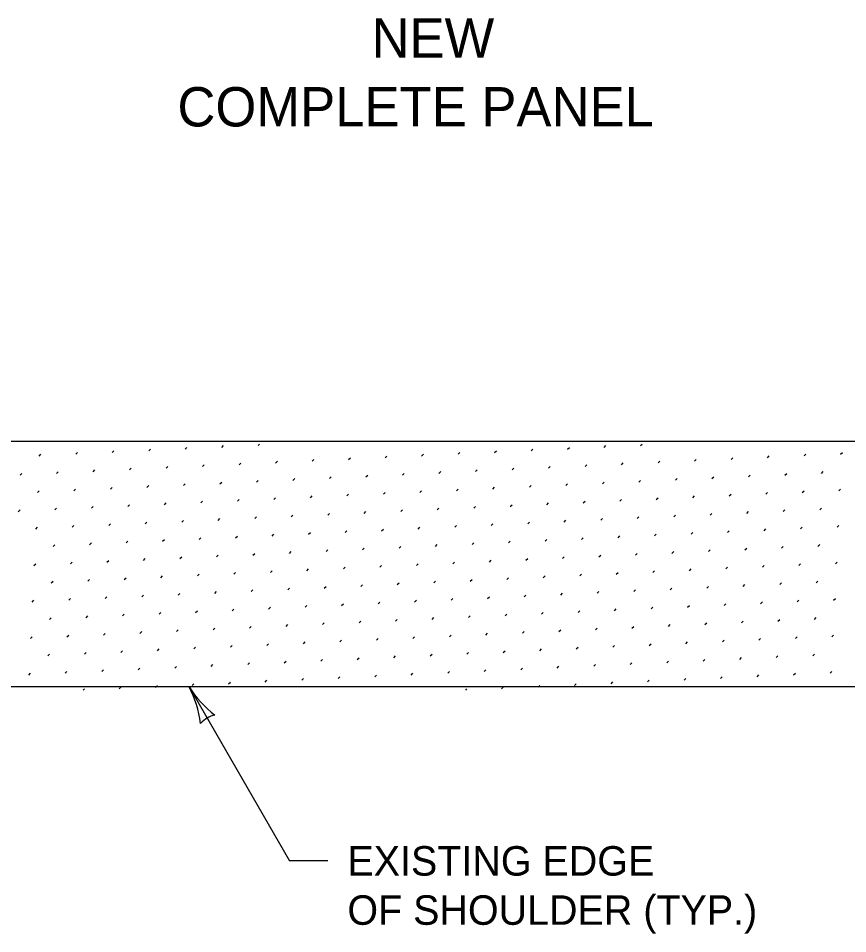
# Model space of a CAD drawing. Extents: x 49991.4 to 50021, y 49987.6 to 50011.4.
# Drawn here: x 50009.904 to 50011.591, y 49993.788 to 49995.65 of the extents above; entities that cross this region are included whole.
import ezdxf

# ---------------------------------------------------------------- set-up
doc = ezdxf.new("R2010")
doc.units = 0
for name, color, linetype in [('Level 1', 7, 'Continuous'), ('Level 10', 7, 'Continuous'), ('Level 2', 7, 'Continuous'), ('Level 3', 7, 'Continuous')]:
    doc.layers.add(name, color=color, linetype=linetype)

msp = doc.modelspace()

# ---------------------------------------------------------------- linework, layer by layer
at = {"layer": 'Level 1'}
for p, q in [((50009.8098, 49994.7903), (50011.6848, 49994.7903)), ((50015.1301, 49994.2903), (50001.3364, 49994.2903))]:
    msp.add_line(p, q, dxfattribs=at)
at = {"layer": 'Level 10'}
for p, q in [((50010.392, 49994.781), (50010.3949, 49994.7838)), ((50011.1699, 49994.7811), (50011.1727, 49994.7838)), ((50010.0208, 49994.7633), (50010.0243, 49994.7668)), ((50010.095, 49994.7668), (50010.0985, 49994.7704)), ((50010.1693, 49994.7704), (50010.1728, 49994.7739)), ((50010.2435, 49994.7739), (50010.247, 49994.7774)), ((50010.3178, 49994.7775), (50010.3213, 49994.781)), ((50010.7986, 49994.7634), (50010.8022, 49994.7669)), ((50010.8729, 49994.7669), (50010.8764, 49994.7704)), ((50010.9471, 49994.7704), (50010.9507, 49994.774)), ((50011.0214, 49994.774), (50011.0249, 49994.7775)), ((50011.0957, 49994.7775), (50011.0992, 49994.7811)), ((50011.5765, 49994.7634), (50011.5801, 49994.767)), ((50009.9465, 49994.7597), (50009.95, 49994.7633)), ((50010.3531, 49994.7421), (50010.3567, 49994.7456)), ((50010.4274, 49994.7456), (50010.4309, 49994.7492)), ((50010.5016, 49994.7492), (50010.5052, 49994.7527)), ((50010.5759, 49994.7527), (50010.5794, 49994.7563)), ((50010.6501, 49994.7563), (50010.6537, 49994.7598)), ((50010.7244, 49994.7598), (50010.7279, 49994.7633)), ((50011.131, 49994.7422), (50011.1345, 49994.7457)), ((50011.2053, 49994.7457), (50011.2088, 49994.7492)), ((50011.2795, 49994.7493), (50011.2831, 49994.7528)), ((50011.3538, 49994.7528), (50011.3573, 49994.7563)), ((50011.428, 49994.7563), (50011.4316, 49994.7599)), ((50011.5023, 49994.7599), (50011.5058, 49994.7634)), ((50009.9819, 49994.7244), (50009.9854, 49994.7279)), ((50010.0561, 49994.7279), (50010.0596, 49994.7315)), ((50010.1304, 49994.7315), (50010.1339, 49994.735)), ((50010.2046, 49994.735), (50010.2082, 49994.7385)), ((50010.2789, 49994.7386), (50010.2824, 49994.7421)), ((50010.7597, 49994.7245), (50010.7633, 49994.728)), ((50010.834, 49994.728), (50010.8375, 49994.7315)), ((50010.9082, 49994.7315), (50010.9118, 49994.7351)), ((50010.9825, 49994.7351), (50010.986, 49994.7386)), ((50011.0568, 49994.7386), (50011.0603, 49994.7422)), ((50011.5376, 49994.7245), (50011.5412, 49994.7281)), ((50009.9076, 49994.7208), (50009.9111, 49994.7244)), ((50010.3885, 49994.7067), (50010.392, 49994.7103)), ((50010.4627, 49994.7103), (50010.4663, 49994.7138)), ((50010.537, 49994.7138), (50010.5405, 49994.7174)), ((50010.6112, 49994.7174), (50010.6148, 49994.7209)), ((50010.6855, 49994.7209), (50010.689, 49994.7244)), ((50011.1664, 49994.7068), (50011.1699, 49994.7103)), ((50011.2406, 49994.7104), (50011.2442, 49994.7139)), ((50011.3149, 49994.7139), (50011.3184, 49994.7174)), ((50011.3891, 49994.7174), (50011.3927, 49994.721)), ((50011.4634, 49994.721), (50011.4669, 49994.7245)), ((50010.0172, 49994.689), (50010.0207, 49994.6926)), ((50010.0915, 49994.6926), (50010.095, 49994.6961)), ((50010.1657, 49994.6961), (50010.1693, 49994.6996)), ((50010.24, 49994.6997), (50010.2435, 49994.7032)), ((50010.3142, 49994.7032), (50010.3178, 49994.7067)), ((50010.7951, 49994.6891), (50010.7986, 49994.6926)), ((50010.8694, 49994.6926), (50010.8729, 49994.6962)), ((50010.9436, 49994.6962), (50010.9471, 49994.6997)), ((50011.0179, 49994.6997), (50011.0214, 49994.7033)), ((50011.0921, 49994.7033), (50011.0956, 49994.7068)), ((50011.573, 49994.6892), (50011.5765, 49994.6927)), ((50009.943, 49994.6855), (50009.9465, 49994.689)), ((50010.3496, 49994.6678), (50010.3531, 49994.6714)), ((50010.4238, 49994.6714), (50010.4274, 49994.6749)), ((50010.4981, 49994.6749), (50010.5016, 49994.6785)), ((50010.5723, 49994.6785), (50010.5759, 49994.682)), ((50010.6466, 49994.682), (50010.6501, 49994.6855)), ((50010.7208, 49994.6856), (50010.7244, 49994.6891)), ((50011.1275, 49994.6679), (50011.131, 49994.6714)), ((50011.2017, 49994.6715), (50011.2053, 49994.675)), ((50011.276, 49994.675), (50011.2795, 49994.6785)), ((50011.3502, 49994.6785), (50011.3538, 49994.6821)), ((50011.4245, 49994.6821), (50011.428, 49994.6856)), ((50011.4987, 49994.6856), (50011.5023, 49994.6892)), ((50009.9783, 49994.6501), (50009.9818, 49994.6537)), ((50010.0526, 49994.6537), (50010.0561, 49994.6572)), ((50010.1268, 49994.6572), (50010.1304, 49994.6608)), ((50010.2011, 49994.6608), (50010.2046, 49994.6643)), ((50010.2753, 49994.6643), (50010.2789, 49994.6678)), ((50010.7562, 49994.6502), (50010.7597, 49994.6537)), ((50010.8305, 49994.6537), (50010.834, 49994.6573)), ((50010.9047, 49994.6573), (50010.9082, 49994.6608)), ((50010.979, 49994.6608), (50010.9825, 49994.6644)), ((50011.0532, 49994.6644), (50011.0567, 49994.6679)), ((50011.5341, 49994.6503), (50011.5376, 49994.6538)), ((50009.9041, 49994.6466), (50009.9076, 49994.6501)), ((50010.3849, 49994.6325), (50010.3885, 49994.636)), ((50010.4592, 49994.636), (50010.4627, 49994.6396)), ((50010.5334, 49994.6396), (50010.537, 49994.6431)), ((50010.6077, 49994.6431), (50010.6112, 49994.6467)), ((50010.6819, 49994.6467), (50010.6855, 49994.6502)), ((50011.1628, 49994.6326), (50011.1664, 49994.6361)), ((50011.2371, 49994.6361), (50011.2406, 49994.6396)), ((50011.3113, 49994.6396), (50011.3149, 49994.6432)), ((50011.3856, 49994.6432), (50011.3891, 49994.6467)), ((50011.4598, 49994.6467), (50011.4634, 49994.6503)), ((50010.0137, 49994.6148), (50010.0172, 49994.6183)), ((50010.0879, 49994.6183), (50010.0915, 49994.6219)), ((50010.1622, 49994.6219), (50010.1657, 49994.6254)), ((50010.2364, 49994.6254), (50010.24, 49994.6289)), ((50010.3107, 49994.6289), (50010.3142, 49994.6325)), ((50010.7916, 49994.6148), (50010.7951, 49994.6184)), ((50010.8658, 49994.6184), (50010.8693, 49994.6219)), ((50010.9401, 49994.6219), (50010.9436, 49994.6255)), ((50011.0143, 49994.6255), (50011.0179, 49994.629)), ((50011.0886, 49994.629), (50011.0921, 49994.6326)), ((50011.5694, 49994.6149), (50011.573, 49994.6185)), ((50009.9394, 49994.6112), (50009.9429, 49994.6148)), ((50010.346, 49994.5936), (50010.3496, 49994.5971)), ((50010.4203, 49994.5971), (50010.4238, 49994.6007)), ((50010.4945, 49994.6007), (50010.4981, 49994.6042)), ((50010.5688, 49994.6042), (50010.5723, 49994.6078)), ((50010.643, 49994.6078), (50010.6466, 49994.6113)), ((50010.7173, 49994.6113), (50010.7208, 49994.6148)), ((50011.1239, 49994.5937), (50011.1275, 49994.5972)), ((50011.1982, 49994.5972), (50011.2017, 49994.6007)), ((50011.2724, 49994.6007), (50011.276, 49994.6043)), ((50011.3467, 49994.6043), (50011.3502, 49994.6078)), ((50011.4209, 49994.6078), (50011.4245, 49994.6114)), ((50011.4952, 49994.6114), (50011.4987, 49994.6149)), ((50009.9748, 49994.5759), (50009.9783, 49994.5794)), ((50010.049, 49994.5794), (50010.0526, 49994.583)), ((50010.1233, 49994.583), (50010.1268, 49994.5865)), ((50010.1975, 49994.5865), (50010.2011, 49994.59)), ((50010.2718, 49994.59), (50010.2753, 49994.5936)), ((50010.7527, 49994.5759), (50010.7562, 49994.5795)), ((50010.8269, 49994.5795), (50010.8304, 49994.583)), ((50010.9012, 49994.583), (50010.9047, 49994.5866)), ((50010.9754, 49994.5866), (50010.979, 49994.5901)), ((50011.0497, 49994.5901), (50011.0532, 49994.5937)), ((50011.5305, 49994.576), (50011.5341, 49994.5796)), ((50010.3814, 49994.5582), (50010.3849, 49994.5618)), ((50010.4556, 49994.5618), (50010.4592, 49994.5653)), ((50010.5299, 49994.5653), (50010.5334, 49994.5689)), ((50010.6042, 49994.5689), (50010.6077, 49994.5724)), ((50010.6784, 49994.5724), (50010.6819, 49994.5759)), ((50011.1593, 49994.5583), (50011.1628, 49994.5618)), ((50011.2335, 49994.5618), (50011.2371, 49994.5654)), ((50011.3078, 49994.5654), (50011.3113, 49994.5689)), ((50011.382, 49994.5689), (50011.3856, 49994.5725)), ((50011.4563, 49994.5725), (50011.4598, 49994.576)), ((50010.0101, 49994.5405), (50010.0137, 49994.5441)), ((50010.0844, 49994.5441), (50010.0879, 49994.5476)), ((50010.1586, 49994.5476), (50010.1622, 49994.5511)), ((50010.2329, 49994.5511), (50010.2364, 49994.5547)), ((50010.3071, 49994.5547), (50010.3107, 49994.5582)), ((50010.788, 49994.5406), (50010.7915, 49994.5441)), ((50010.8623, 49994.5441), (50010.8658, 49994.5477)), ((50010.9365, 49994.5477), (50010.9401, 49994.5512)), ((50011.0108, 49994.5512), (50011.0143, 49994.5548)), ((50011.085, 49994.5548), (50011.0886, 49994.5583)), ((50011.5659, 49994.5407), (50011.5694, 49994.5442)), ((50009.9359, 49994.537), (50009.9394, 49994.5405)), ((50010.3425, 49994.5193), (50010.346, 49994.5229)), ((50010.4167, 49994.5229), (50010.4203, 49994.5264)), ((50010.491, 49994.5264), (50010.4945, 49994.53)), ((50010.5653, 49994.53), (50010.5688, 49994.5335)), ((50010.6395, 49994.5335), (50010.643, 49994.537)), ((50010.7138, 49994.537), (50010.7173, 49994.5406)), ((50011.1204, 49994.5194), (50011.1239, 49994.5229)), ((50011.1946, 49994.5229), (50011.1982, 49994.5265)), ((50011.2689, 49994.5265), (50011.2724, 49994.53)), ((50011.3431, 49994.53), (50011.3467, 49994.5336)), ((50011.4174, 49994.5336), (50011.4209, 49994.5371)), ((50011.4916, 49994.5371), (50011.4952, 49994.5407)), ((50009.9712, 49994.5016), (50009.9748, 49994.5052)), ((50010.0455, 49994.5052), (50010.049, 49994.5087)), ((50010.1197, 49994.5087), (50010.1233, 49994.5122)), ((50010.194, 49994.5123), (50010.1975, 49994.5158)), ((50010.2682, 49994.5158), (50010.2718, 49994.5193)), ((50010.7491, 49994.5017), (50010.7527, 49994.5052)), ((50010.8234, 49994.5052), (50010.8269, 49994.5088)), ((50010.8976, 49994.5088), (50010.9012, 49994.5123)), ((50010.9719, 49994.5123), (50010.9754, 49994.5159)), ((50011.0461, 49994.5159), (50011.0497, 49994.5194)), ((50011.527, 49994.5018), (50011.5305, 49994.5053)), ((50010.3778, 49994.484), (50010.3814, 49994.4875)), ((50010.4521, 49994.4875), (50010.4556, 49994.4911)), ((50010.5264, 49994.4911), (50010.5299, 49994.4946)), ((50010.6006, 49994.4946), (50010.6041, 49994.4981)), ((50010.6749, 49994.4982), (50010.6784, 49994.5017)), ((50011.1557, 49994.4841), (50011.1593, 49994.4876)), ((50011.23, 49994.4876), (50011.2335, 49994.4911)), ((50011.3042, 49994.4911), (50011.3078, 49994.4947)), ((50011.3785, 49994.4947), (50011.382, 49994.4982)), ((50011.4528, 49994.4982), (50011.4563, 49994.5018)), ((50010.0066, 49994.4663), (50010.0101, 49994.4698)), ((50010.0808, 49994.4698), (50010.0844, 49994.4733)), ((50010.1551, 49994.4734), (50010.1586, 49994.4769)), ((50010.2293, 49994.4769), (50010.2329, 49994.4804)), ((50010.3036, 49994.4804), (50010.3071, 49994.484)), ((50010.7102, 49994.4628), (50010.7138, 49994.4663)), ((50010.7845, 49994.4663), (50010.788, 49994.4699)), ((50010.8587, 49994.4699), (50010.8623, 49994.4734)), ((50010.933, 49994.4734), (50010.9365, 49994.477)), ((50011.0072, 49994.477), (50011.0108, 49994.4805)), ((50011.0815, 49994.4805), (50011.085, 49994.484)), ((50011.4881, 49994.4629), (50011.4916, 49994.4664)), ((50011.5624, 49994.4664), (50011.5659, 49994.4699)), ((50009.9323, 49994.4627), (50009.9359, 49994.4663)), ((50010.339, 49994.4451), (50010.3425, 49994.4486)), ((50010.4132, 49994.4486), (50010.4167, 49994.4522)), ((50010.4875, 49994.4522), (50010.491, 49994.4557)), ((50010.5617, 49994.4557), (50010.5652, 49994.4592)), ((50010.636, 49994.4593), (50010.6395, 49994.4628)), ((50011.1168, 49994.4452), (50011.1204, 49994.4487)), ((50011.1911, 49994.4487), (50011.1946, 49994.4522)), ((50011.2653, 49994.4522), (50011.2689, 49994.4558)), ((50011.3396, 49994.4558), (50011.3431, 49994.4593)), ((50011.4139, 49994.4593), (50011.4174, 49994.4629)), ((50009.9677, 49994.4274), (50009.9712, 49994.4309)), ((50010.0419, 49994.4309), (50010.0455, 49994.4344)), ((50010.1162, 49994.4345), (50010.1197, 49994.438)), ((50010.1904, 49994.438), (50010.194, 49994.4415)), ((50010.2647, 49994.4415), (50010.2682, 49994.4451)), ((50010.7456, 49994.4274), (50010.7491, 49994.431)), ((50010.8198, 49994.431), (50010.8234, 49994.4345)), ((50010.8941, 49994.4345), (50010.8976, 49994.4381)), ((50010.9683, 49994.4381), (50010.9719, 49994.4416)), ((50011.0426, 49994.4416), (50011.0461, 49994.4451)), ((50011.5235, 49994.4275), (50011.527, 49994.431)), ((50010.3743, 49994.4097), (50010.3778, 49994.4133)), ((50010.4486, 49994.4133), (50010.4521, 49994.4168)), ((50010.5228, 49994.4168), (50010.5263, 49994.4203)), ((50010.5971, 49994.4204), (50010.6006, 49994.4239)), ((50010.6713, 49994.4239), (50010.6749, 49994.4274)), ((50011.1522, 49994.4098), (50011.1557, 49994.4133)), ((50011.2264, 49994.4133), (50011.23, 49994.4169)), ((50011.3007, 49994.4169), (50011.3042, 49994.4204)), ((50011.375, 49994.4204), (50011.3785, 49994.424)), ((50011.4492, 49994.424), (50011.4527, 49994.4275)), ((50009.9288, 49994.3885), (50009.9323, 49994.392)), ((50010.003, 49994.392), (50010.0066, 49994.3956)), ((50010.0773, 49994.3956), (50010.0808, 49994.3991)), ((50010.1515, 49994.3991), (50010.1551, 49994.4026)), ((50010.2258, 49994.4026), (50010.2293, 49994.4062)), ((50010.3001, 49994.4062), (50010.3036, 49994.4097)), ((50010.7067, 49994.3885), (50010.7102, 49994.3921)), ((50010.7809, 49994.3921), (50010.7845, 49994.3956)), ((50010.8552, 49994.3956), (50010.8587, 49994.3992)), ((50010.9294, 49994.3992), (50010.933, 49994.4027)), ((50011.0037, 49994.4027), (50011.0072, 49994.4062)), ((50011.0779, 49994.4063), (50011.0815, 49994.4098)), ((50011.4846, 49994.3886), (50011.4881, 49994.3921)), ((50011.5588, 49994.3922), (50011.5624, 49994.3957)), ((50010.3354, 49994.3708), (50010.3389, 49994.3744)), ((50010.4097, 49994.3744), (50010.4132, 49994.3779)), ((50010.4839, 49994.3779), (50010.4875, 49994.3815)), ((50010.5582, 49994.3815), (50010.5617, 49994.385)), ((50010.6324, 49994.385), (50010.636, 49994.3885)), ((50011.1133, 49994.3709), (50011.1168, 49994.3744)), ((50011.1875, 49994.3744), (50011.1911, 49994.378)), ((50011.2618, 49994.378), (50011.2653, 49994.3815)), ((50011.3361, 49994.3815), (50011.3396, 49994.3851)), ((50011.4103, 49994.3851), (50011.4138, 49994.3886)), ((50009.9641, 49994.3531), (50009.9677, 49994.3567)), ((50010.0384, 49994.3567), (50010.0419, 49994.3602)), ((50010.1126, 49994.3602), (50010.1162, 49994.3637)), ((50010.1869, 49994.3637), (50010.1904, 49994.3673)), ((50010.2612, 49994.3673), (50010.2647, 49994.3708)), ((50010.742, 49994.3532), (50010.7456, 49994.3567)), ((50010.8163, 49994.3567), (50010.8198, 49994.3603)), ((50010.8905, 49994.3603), (50010.8941, 49994.3638)), ((50010.9648, 49994.3638), (50010.9683, 49994.3674)), ((50011.039, 49994.3674), (50011.0426, 49994.3709)), ((50011.5199, 49994.3533), (50011.5235, 49994.3568)), ((50010.3708, 49994.3355), (50010.3743, 49994.339)), ((50010.445, 49994.339), (50010.4486, 49994.3426)), ((50010.5193, 49994.3426), (50010.5228, 49994.3461)), ((50010.5935, 49994.3461), (50010.5971, 49994.3496)), ((50010.6678, 49994.3496), (50010.6713, 49994.3532)), ((50011.1487, 49994.3355), (50011.1522, 49994.3391)), ((50011.2229, 49994.3391), (50011.2264, 49994.3426)), ((50011.2972, 49994.3426), (50011.3007, 49994.3462)), ((50011.3714, 49994.3462), (50011.3749, 49994.3497)), ((50011.4457, 49994.3497), (50011.4492, 49994.3533)), ((50009.9252, 49994.3142), (50009.9288, 49994.3178)), ((50009.9995, 49994.3178), (50010.003, 49994.3213)), ((50010.0738, 49994.3213), (50010.0773, 49994.3248)), ((50010.148, 49994.3248), (50010.1515, 49994.3284)), ((50010.2223, 49994.3284), (50010.2258, 49994.3319)), ((50010.2965, 49994.3319), (50010.3, 49994.3355)), ((50010.7031, 49994.3143), (50010.7067, 49994.3178)), ((50010.7774, 49994.3178), (50010.7809, 49994.3214)), ((50010.8516, 49994.3214), (50010.8552, 49994.3249)), ((50010.9259, 49994.3249), (50010.9294, 49994.3285)), ((50011.0001, 49994.3285), (50011.0037, 49994.332)), ((50011.0744, 49994.332), (50011.0779, 49994.3355)), ((50011.481, 49994.3144), (50011.4846, 49994.3179)), ((50011.5553, 49994.3179), (50011.5588, 49994.3214)), ((50010.3319, 49994.2966), (50010.3354, 49994.3001)), ((50010.4061, 49994.3001), (50010.4097, 49994.3037)), ((50010.4804, 49994.3037), (50010.4839, 49994.3072)), ((50010.5546, 49994.3072), (50010.5582, 49994.3107)), ((50010.6289, 49994.3107), (50010.6324, 49994.3143)), ((50011.1098, 49994.2966), (50011.1133, 49994.3002)), ((50011.184, 49994.3002), (50011.1875, 49994.3037)), ((50011.2583, 49994.3037), (50011.2618, 49994.3073)), ((50011.3325, 49994.3073), (50011.336, 49994.3108)), ((50011.4068, 49994.3108), (50011.4103, 49994.3144)), ((50010.0363, 49994.2838), (50010.0384, 49994.2859)), ((50010.1091, 49994.2859), (50010.1126, 49994.2895)), ((50010.1834, 49994.2895), (50010.1869, 49994.293)), ((50010.2576, 49994.293), (50010.2611, 49994.2966)), ((50010.8141, 49994.2838), (50010.8163, 49994.286)), ((50010.887, 49994.286), (50010.8905, 49994.2896)), ((50010.9612, 49994.2896), (50010.9648, 49994.2931)), ((50011.0355, 49994.2931), (50011.039, 49994.2966))]:
    msp.add_line(p, q, dxfattribs=at)
at = {"layer": 'Level 3'}
for p in [(50010.2514, 49994.2903), (50010.5334, 49993.9362)]:
    msp.add_line(p, (50010.4559, 49993.9362), dxfattribs=at)
for centre, radius, start, end in [((50010.0545, 49994.1871), 0.2223, 7.456, 27.6395), ((50010.4472, 49994.4166), 0.233, 212.8273, 232.0772), ((50010.3155, 49994.1792), 0.0548, 102.1388, 137.8612)]:
    msp.add_arc(centre, radius, start, end, dxfattribs=at)

# ---------------------------------------------------------------- texts
at = {"layer": 'Level 2'}
for s, height, p in [('NEW', 0.08, (50010.6225, 49995.5703)), ('COMPLETE PANEL', 0.08, (50010.2277, 49995.4303)), ('EXISTING EDGE ', 0.06, (50010.5734, 49993.9062)), ('OF SHOULDER (TYP.)', 0.06, (50010.5734, 49993.8062))]:
    msp.add_text(s, height=height, dxfattribs=at).set_placement(p)

doc.saveas('drawing.dxf')
